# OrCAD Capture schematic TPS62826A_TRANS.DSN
size D; title: TPS62826A 2.4-V to 5.5-V input 3-A Step-Down Converter with; rev: 1.0; note: Datasheet: SLVSEF9D                      EVM: SLVUBY3; note: Synchronous Step Down Converter
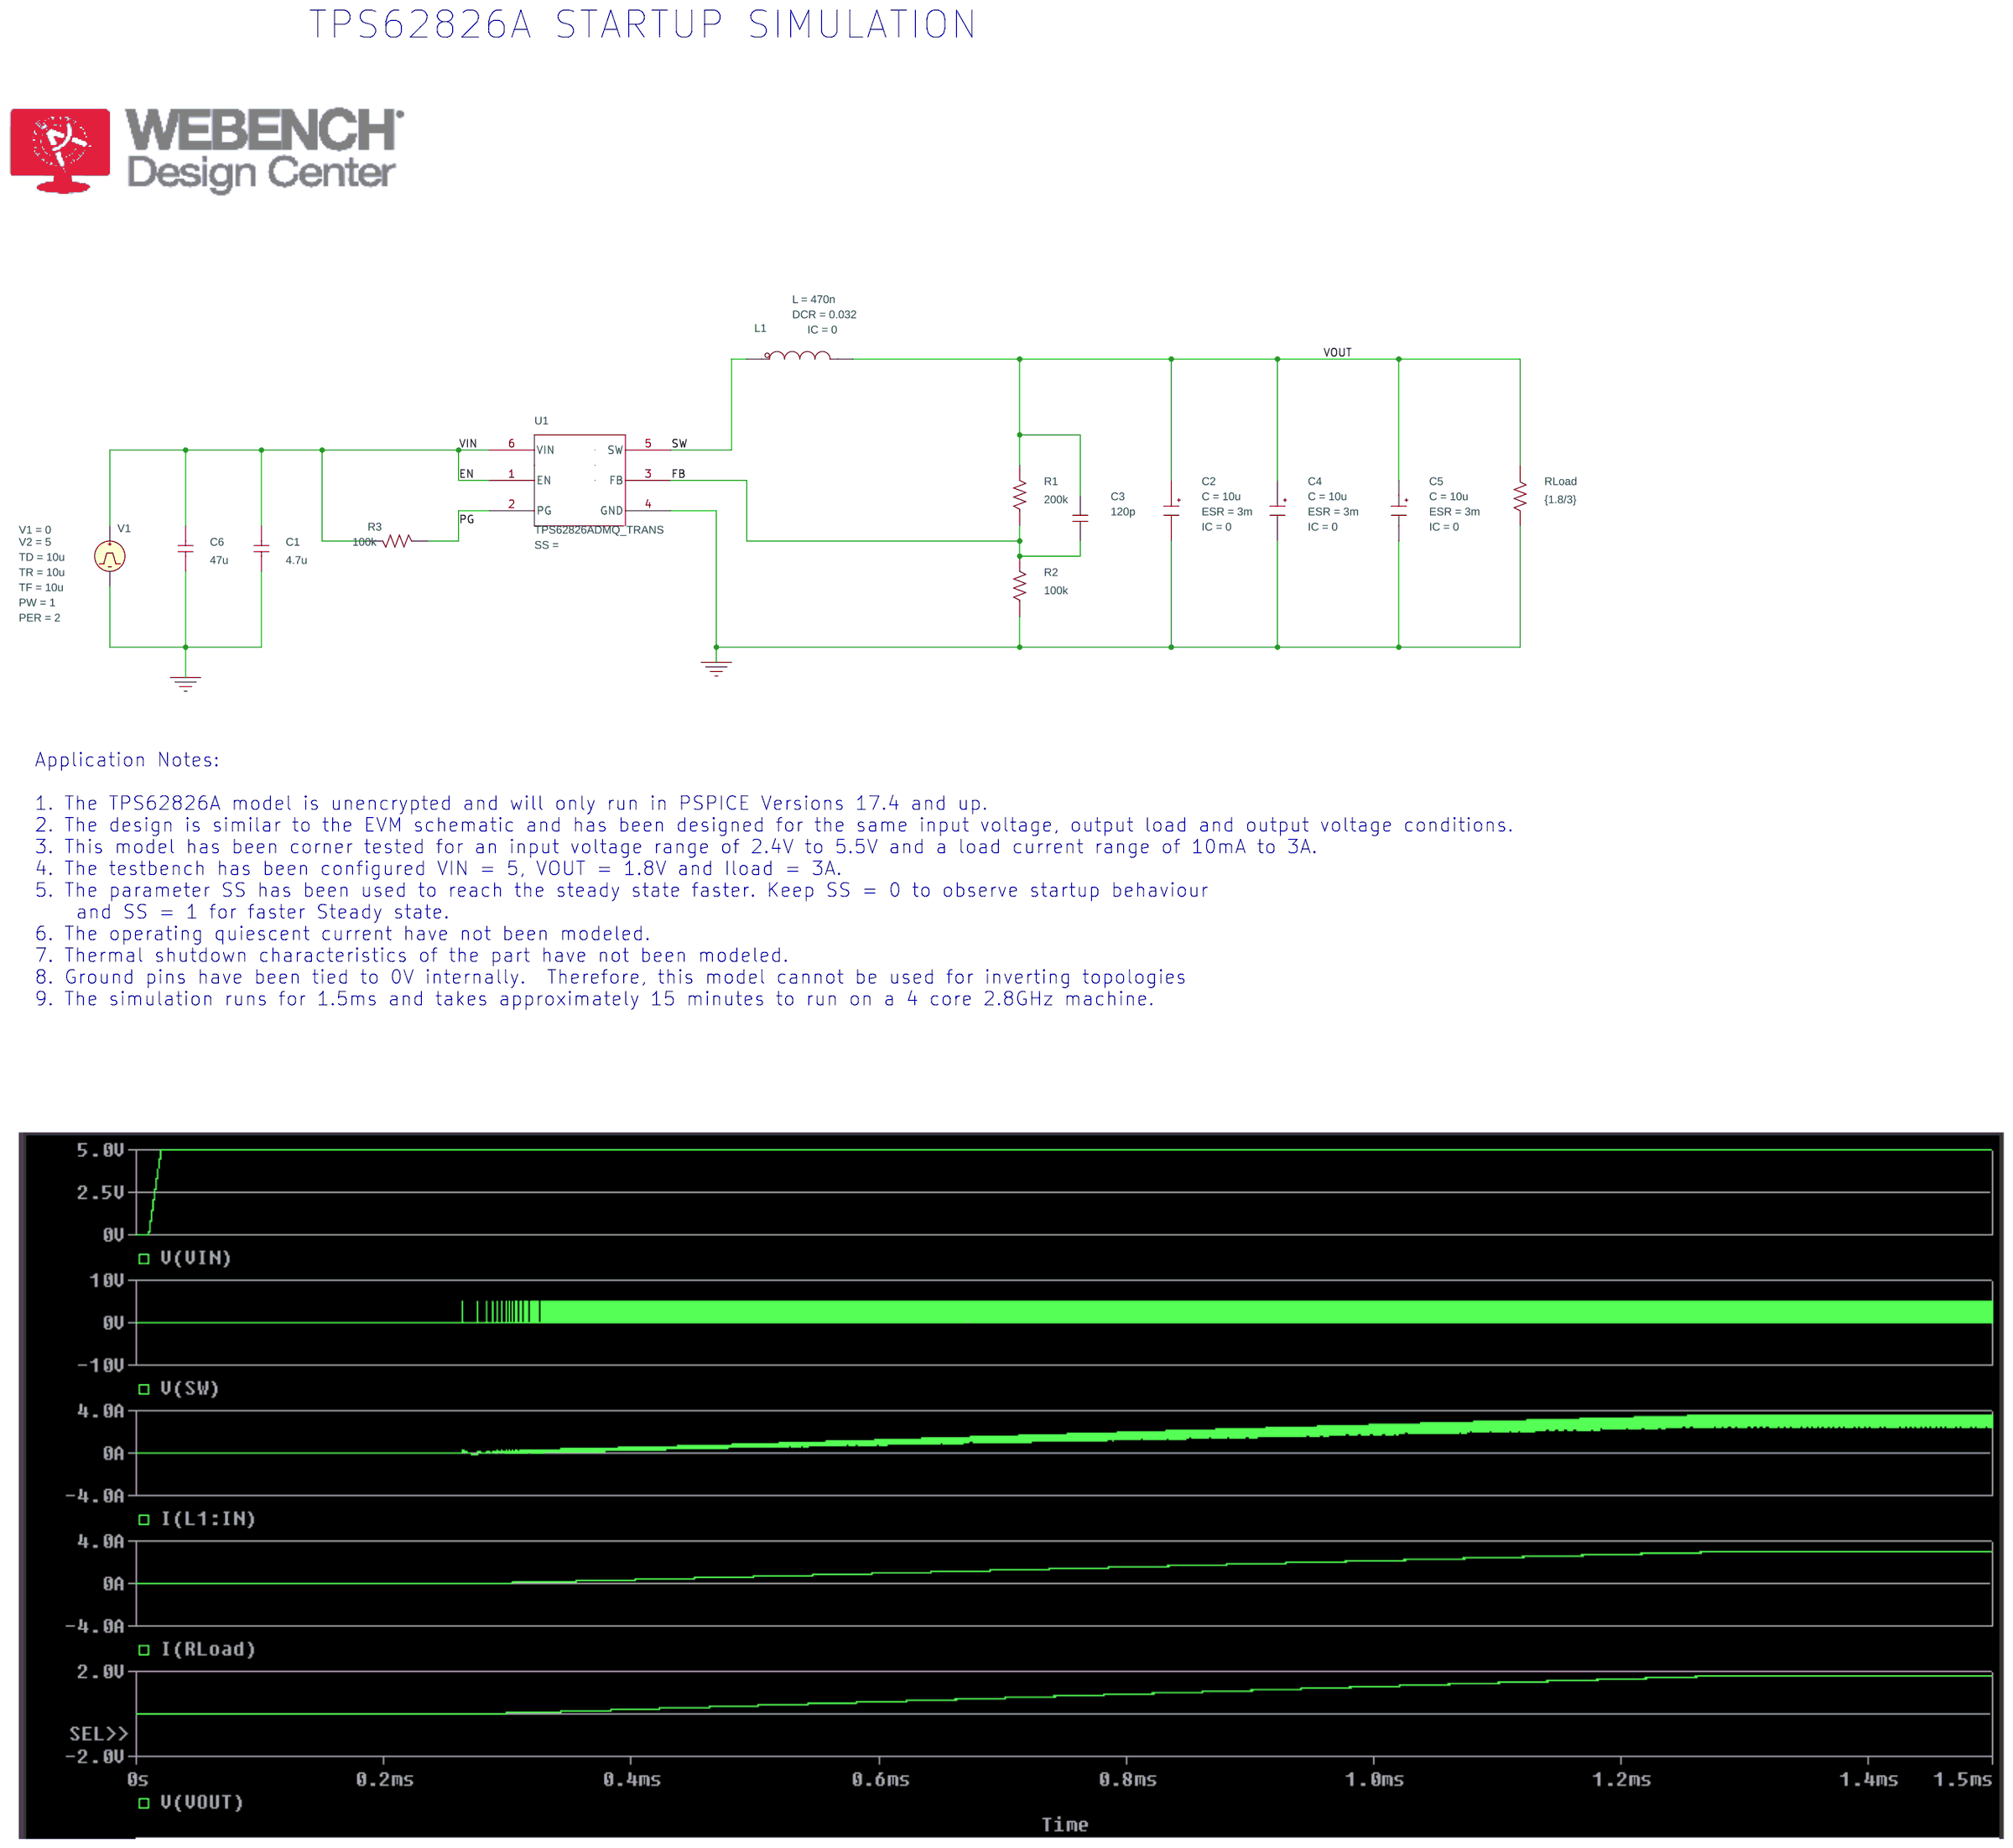
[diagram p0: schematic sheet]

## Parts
C1  4.7u  [RAD/CK05]
C2  CESR
C3  120p  [RAD/CK05]
C4  CESR
C5  CESR
C6  47u  [RAD/CK05]
L1  LDCR
R1  200k  [AX/RC05]
R2  100k  [AX/RC05]
R3  100k  [AX/RC05]
RLoad  {1.8/3}  [AX/RC05]
U1  TPS62826ADMQ_TRANS  [DMQ0006A-MFG]
V1  VPULSE

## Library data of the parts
C1 C6 = C: IC: 0
C2 C4 C5 = CESR_0: C: 10u; ESR: 3m; IC: 0; PSpiceTemplate: X^@REFDES %IN %OUT @MODEL PARAMS:  ?C|C=@C||C=100u|  ?ESR|ESR=@ESR||ESR=0.01| ?X|X=@X||X=2|  ?IC|IC=@IC||IC=2|; X: 1
C3 = C
L1 = LDCR_0: DCR: 0.032; IC: 0; L: 470n; PSpiceTemplate: X^@REFDES %IN %OUT @MODEL PARAMS:  ?L|L=@L||L=1u|  ?DCR|DCR=@DCR||DCR=0.01| ?IC|IC=@IC||IC=0|
R1-R3 RLoad = R
U1 = TPS62826ADMQ_TRANS
V1 = VPULSE: PER: 2; PW: 1; TD: 10u; TF: 10u; TR: 10u; V1: 0; V2: 5

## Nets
0: C1.2 C2.3(OUT) C4.3(OUT) C5.3(OUT) C6.2 R2.1 RLoad.2 U1.4(GND) V1.2(-)
EN: C1.1 C6.1 R3.2 U1.1(EN) U1.6(VIN) V1.1(+)
FB: C3.2 R1.1 R2.2 U1.3(FB)
PG: R3.1 U1.2(PG)
SW: L1.1(IN) U1.5(SW)
VOUT: C2.1(IN) C3.1 C4.1(IN) C5.1(IN) L1.3(OUT) R1.2 RLoad.1

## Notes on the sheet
- TPS62826A STARTUP SIMULATION
- Application Notes:
  1. The TPS62826A model is unencrypted and will only run in PSPICE Versions 17.4 and up.
  2. The design is similar to the EVM schematic and has been designed for the same input voltage, output load and output voltage conditions.
  3. This model has been corner tested for an input voltage range of 2.4V to 5.5V and a load current range of 10mA to 3A.
  4. The testbench has been configured VIN = 5, VOUT = 1.8V and Iload = 3A.
  5. The parameter SS has been used to reach the steady state faster. Keep SS = 0 to observe startup behaviour
      and SS = 1 for faster Steady state.
  6. The operating quiescent current have not been modeled.
  7. Thermal shutdown characteristics of the part have not been modeled.
  8. Ground pins have been tied to 0V internally.  Therefore, this model cannot be used for inverting topologies
  9. The simulation runs for 1.5ms and takes approximately 15 minutes to run on a 4 core 2.8GHz machine.
